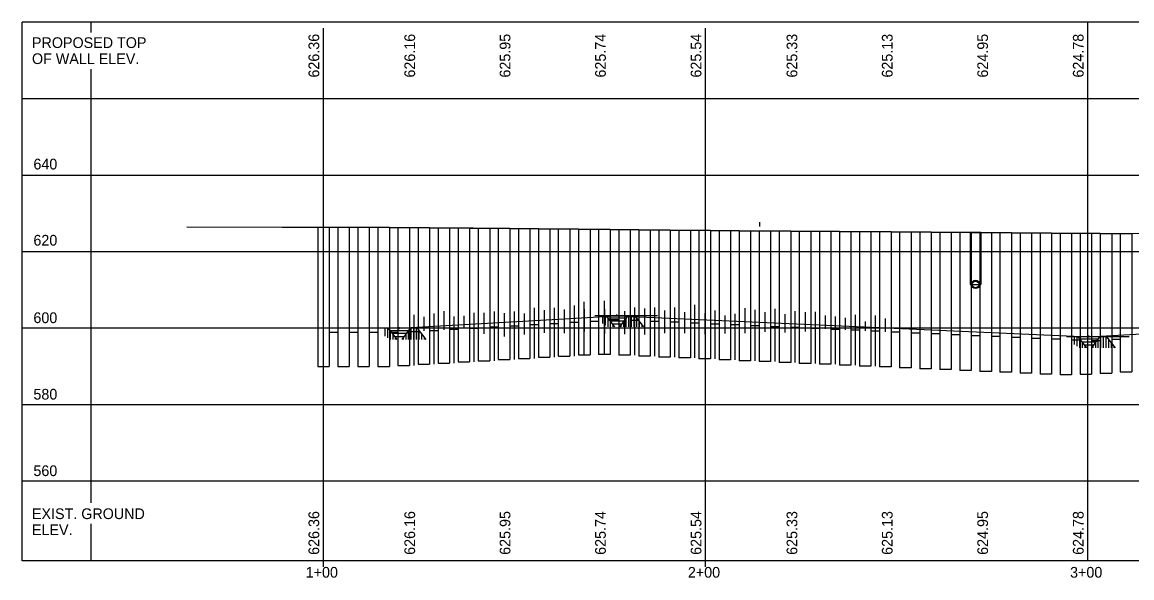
# Model space of a CAD drawing. Extents: x 2267596 to 2268160, y 712626 to 714793.
# Drawn here: x 2267595.7 to 2267886, y 713757.9 to 713903.3 of the extents above; entities that cross this region are included whole.
import ezdxf

# ---------------------------------------------------------------- set-up
doc = ezdxf.new("R2010")
doc.units = 0
for name, color, linetype in [('BR_P_Gen_Text', 7, 'Continuous'), ('BR_P_Sub_Deep_Hidden', 7, 'Continuous'), ('BR_P_Sub_Deep_Object', 7, 'Continuous'), ('Default', 7, 'Continuous'), ('DR_P_Storm_Sewer', 7, 'Continuous'), ('GE_X_Alignment', 7, 'Continuous'), ('SC_Scratch1', 7, 'Continuous'), ('SC_Scratch10', 7, 'Continuous'), ('SC_Scratch9', 7, 'Continuous'), ('SC_Shading3', 7, 'Continuous'), ('SH_Major_Grid_Line', 7, 'Continuous'), ('XS_X_Ground_Line', 7, 'Continuous')]:
    doc.layers.add(name, color=color, linetype=linetype)

msp = doc.modelspace()

# ---------------------------------------------------------------- linework, layer by layer
at = {"layer": 'BR_P_Sub_Deep_Hidden'}
for p, q in [((2267843.78, 713848.35), (2267843.78, 713834.69)), ((2267846.53, 713848.32), (2267846.53, 713834.69)), ((2267844.08, 713834.69), (2267843.78, 713834.69)), ((2267846.53, 713834.69), (2267846.25, 713834.69))]:
    msp.add_line(p, q, dxfattribs=at)
at = {"layer": 'BR_P_Sub_Deep_Object'}
for p, q in [((2267673.03, 713849.7), (2267676.03, 713849.69)), ((2267673.03, 713849.69), (2267673.03, 713813.21)), ((2267676.03, 713849.69), (2267676.03, 713813.21)), ((2267676.03, 713849.69), (2267678.28, 713849.69)), ((2267678.28, 713849.69), (2267678.28, 713813.21)), ((2267678.28, 713849.69), (2267681.28, 713849.69)), ((2267681.28, 713849.69), (2267681.28, 713813.21)), ((2267681.28, 713849.69), (2267683.53, 713849.69)), ((2267683.53, 713849.69), (2267686.53, 713849.69)), ((2267683.53, 713849.68), (2267683.53, 713813.21)), ((2267686.53, 713849.69), (2267688.78, 713849.69)), ((2267686.53, 713849.68), (2267686.53, 713813.21)), ((2267688.78, 713849.68), (2267688.78, 713813.22)), ((2267688.78, 713849.66), (2267691.78, 713849.66)), ((2267691.78, 713849.66), (2267691.78, 713813.22)), ((2267691.78, 713849.63), (2267694.03, 713849.63)), ((2267694.03, 713849.63), (2267694.03, 713813.52)), ((2267694.03, 713849.62), (2267697.03, 713849.62)), ((2267697.03, 713849.61), (2267697.03, 713813.52)), ((2267697.03, 713849.59), (2267699.28, 713849.59)), ((2267699.28, 713849.59), (2267699.28, 713813.83)), ((2267699.28, 713849.57), (2267702.28, 713849.57)), ((2267702.28, 713849.57), (2267702.28, 713813.83)), ((2267702.28, 713849.54), (2267704.53, 713849.54)), ((2267704.53, 713849.54), (2267704.53, 713814.13)), ((2267704.53, 713849.52), (2267707.53, 713849.52)), ((2267707.53, 713849.52), (2267707.53, 713814.13)), ((2267707.53, 713849.5), (2267709.78, 713849.5)), ((2267709.78, 713849.49), (2267709.78, 713814.44)), ((2267709.78, 713849.48), (2267712.78, 713849.48)), ((2267712.78, 713849.47), (2267712.78, 713814.44)), ((2267712.78, 713849.45), (2267715.03, 713849.45)), ((2267715.03, 713849.45), (2267715.03, 713814.74)), ((2267715.03, 713849.43), (2267718.03, 713849.43)), ((2267718.03, 713849.42), (2267718.03, 713814.74)), ((2267718.03, 713849.4), (2267720.28, 713849.4)), ((2267720.28, 713849.4), (2267720.28, 713815.04)), ((2267720.28, 713849.38), (2267723.28, 713849.38)), ((2267723.28, 713849.37), (2267723.28, 713815.04)), ((2267723.28, 713849.35), (2267725.53, 713849.35)), ((2267725.53, 713849.35), (2267725.53, 713815.35)), ((2267725.53, 713849.33), (2267728.53, 713849.33)), ((2267728.53, 713849.32), (2267728.53, 713815.35)), ((2267728.53, 713849.3), (2267730.78, 713849.3)), ((2267730.78, 713849.3), (2267730.78, 713815.65)), ((2267730.78, 713849.28), (2267733.78, 713849.28)), ((2267733.78, 713849.27), (2267733.78, 713815.65)), ((2267733.78, 713849.25), (2267736.03, 713849.25)), ((2267736.03, 713815.96), (2267736.03, 713849.24)), ((2267736.03, 713849.23), (2267739.03, 713849.23)), ((2267739.03, 713849.22), (2267739.03, 713815.96)), ((2267739.03, 713849.2), (2267741.28, 713849.2)), ((2267741.28, 713849.19), (2267741.28, 713816.26)), ((2267741.28, 713849.17), (2267744.28, 713849.17)), ((2267744.28, 713849.17), (2267744.28, 713816.26)), ((2267744.28, 713849.14), (2267746.53, 713849.14)), ((2267746.53, 713849.14), (2267746.53, 713816.37)), ((2267746.53, 713849.12), (2267749.53, 713849.12)), ((2267749.53, 713849.12), (2267749.53, 713816.37)), ((2267749.53, 713849.09), (2267751.78, 713849.09)), ((2267751.78, 713849.09), (2267751.78, 713816.14)), ((2267751.78, 713849.07), (2267754.78, 713849.07)), ((2267754.78, 713849.07), (2267754.78, 713816.14)), ((2267754.78, 713849.04), (2267757.03, 713849.04)), ((2267757.03, 713849.04), (2267757.03, 713815.9)), ((2267757.03, 713849.02), (2267760.03, 713849.02)), ((2267760.03, 713849.01), (2267760.03, 713815.9)), ((2267760.03, 713848.99), (2267762.28, 713848.99)), ((2267762.28, 713848.98), (2267762.28, 713815.67)), ((2267762.28, 713848.96), (2267765.28, 713848.96)), ((2267765.28, 713848.96), (2267765.28, 713815.67)), ((2267765.28, 713848.93), (2267767.53, 713848.93)), ((2267767.53, 713848.93), (2267767.53, 713815.44)), ((2267767.53, 713848.91), (2267770.53, 713848.91)), ((2267770.53, 713848.91), (2267770.53, 713815.44)), ((2267770.53, 713848.88), (2267772.78, 713848.88)), ((2267772.78, 713848.88), (2267772.78, 713815.2)), ((2267772.78, 713848.86), (2267775.78, 713848.86)), ((2267775.78, 713848.86), (2267775.78, 713815.2)), ((2267775.78, 713848.83), (2267778.03, 713848.83)), ((2267778.03, 713848.83), (2267778.03, 713814.97)), ((2267778.03, 713848.81), (2267781.03, 713848.81)), ((2267781.03, 713848.8), (2267781.03, 713814.97)), ((2267781.03, 713848.78), (2267783.28, 713848.78)), ((2267783.28, 713848.77), (2267783.28, 713814.73)), ((2267783.28, 713848.75), (2267786.28, 713848.75)), ((2267786.28, 713848.75), (2267786.28, 713814.73)), ((2267786.28, 713848.72), (2267788.53, 713848.72)), ((2267788.53, 713848.72), (2267788.53, 713814.5)), ((2267788.53, 713848.71), (2267791.53, 713848.71)), ((2267791.53, 713848.71), (2267791.53, 713814.5)), ((2267791.53, 713848.69), (2267793.78, 713848.69)), ((2267793.78, 713848.69), (2267793.78, 713814.27)), ((2267793.78, 713848.68), (2267796.78, 713848.68)), ((2267796.78, 713848.67), (2267796.78, 713814.27)), ((2267796.78, 713848.66), (2267799.03, 713848.66)), ((2267799.03, 713848.65), (2267799.03, 713814.03)), ((2267799.03, 713848.64), (2267802.03, 713848.64)), ((2267802.03, 713848.64), (2267802.03, 713814.03)), ((2267802.03, 713848.62), (2267804.28, 713848.62)), ((2267804.28, 713848.62), (2267804.28, 713813.8)), ((2267804.28, 713848.61), (2267807.28, 713848.61)), ((2267807.28, 713848.61), (2267807.28, 713813.8)), ((2267807.28, 713848.59), (2267809.53, 713848.59)), ((2267809.53, 713848.59), (2267809.53, 713813.56)), ((2267809.53, 713848.58), (2267812.53, 713848.58)), ((2267812.53, 713848.57), (2267812.53, 713813.56)), ((2267812.53, 713848.56), (2267814.78, 713848.56)), ((2267814.78, 713848.55), (2267814.78, 713813.33)), ((2267814.78, 713848.54), (2267817.78, 713848.54)), ((2267817.78, 713848.54), (2267817.78, 713813.33)), ((2267817.78, 713848.52), (2267820.03, 713848.52)), ((2267820.03, 713848.52), (2267820.03, 713813.1)), ((2267820.03, 713848.5), (2267823.03, 713848.5)), ((2267823.03, 713848.5), (2267823.03, 713813.1)), ((2267823.03, 713848.48), (2267825.28, 713848.48)), ((2267825.28, 713848.48), (2267825.28, 713812.86)), ((2267825.28, 713848.47), (2267828.28, 713848.47)), ((2267828.28, 713848.47), (2267828.28, 713812.86)), ((2267828.28, 713848.45), (2267830.53, 713848.45)), ((2267830.53, 713848.45), (2267830.53, 713812.63)), ((2267830.53, 713848.43), (2267833.53, 713848.43)), ((2267833.53, 713848.43), (2267833.53, 713812.63)), ((2267833.53, 713848.41), (2267835.78, 713848.41)), ((2267835.78, 713848.41), (2267835.78, 713812.4)), ((2267835.78, 713848.4), (2267838.78, 713848.4)), ((2267838.78, 713848.39), (2267838.78, 713812.4)), ((2267838.78, 713848.37), (2267841.03, 713848.37)), ((2267841.03, 713848.37), (2267841.03, 713812.16)), ((2267841.03, 713848.35), (2267844.03, 713848.35)), ((2267844.03, 713848.35), (2267844.03, 713812.16)), ((2267844.03, 713848.32), (2267846.28, 713848.32)), ((2267846.28, 713848.32), (2267846.28, 713811.93)), ((2267846.28, 713848.3), (2267849.28, 713848.3)), ((2267849.28, 713848.29), (2267849.28, 713811.93)), ((2267849.28, 713848.27), (2267851.53, 713848.27)), ((2267851.53, 713848.27), (2267851.53, 713811.69)), ((2267851.53, 713848.25), (2267854.53, 713848.25)), ((2267854.53, 713848.24), (2267854.53, 713811.69)), ((2267854.53, 713848.22), (2267856.78, 713848.22)), ((2267856.78, 713848.22), (2267856.78, 713811.46)), ((2267856.78, 713848.2), (2267859.78, 713848.2)), ((2267859.78, 713848.19), (2267859.78, 713811.46)), ((2267859.78, 713848.17), (2267862.03, 713848.17)), ((2267862.03, 713848.17), (2267862.03, 713811.23)), ((2267862.03, 713848.15), (2267865.03, 713848.15)), ((2267865.03, 713848.15), (2267865.03, 713811.23)), ((2267865.03, 713848.13), (2267867.28, 713848.13)), ((2267867.28, 713848.13), (2267867.28, 713811.04)), ((2267867.28, 713848.12), (2267870.28, 713848.12)), ((2267870.28, 713848.12), (2267870.28, 713811.04)), ((2267870.28, 713848.1), (2267872.53, 713848.1)), ((2267872.53, 713848.1), (2267872.53, 713811.21)), ((2267872.53, 713848.09), (2267875.53, 713848.09)), ((2267875.53, 713848.08), (2267875.53, 713811.21)), ((2267875.53, 713848.07), (2267877.78, 713848.07)), ((2267877.78, 713848.07), (2267877.78, 713811.5)), ((2267877.78, 713848.05), (2267880.78, 713848.05)), ((2267880.78, 713848.05), (2267880.78, 713811.5)), ((2267880.78, 713848.04), (2267883.03, 713848.04)), ((2267883.03, 713848.03), (2267883.03, 713811.8)), ((2267883.03, 713848.02), (2267886.03, 713848.02)), ((2267886.03, 713848.02), (2267886.03, 713811.8)), ((2267744.28, 713825.1), (2267746.53, 713825.1)), ((2267751.78, 713825.41), (2267749.53, 713825.41)), ((2267757.03, 713825.26), (2267754.78, 713825.26)), ((2267762.28, 713825.02), (2267760.03, 713825.02)), ((2267676.03, 713822.21), (2267678.28, 713822.21)), ((2267681.28, 713822.21), (2267683.53, 713822.21)), ((2267686.53, 713822.21), (2267688.78, 713822.21)), ((2267691.78, 713822.21), (2267694.03, 713822.21)), ((2267697.03, 713822.37), (2267699.28, 713822.37)), ((2267702.28, 713822.67), (2267704.53, 713822.67)), ((2267707.53, 713822.97), (2267709.78, 713822.97)), ((2267712.78, 713823.28), (2267715.03, 713823.28)), ((2267718.03, 713823.58), (2267720.28, 713823.58)), ((2267723.28, 713823.89), (2267725.53, 713823.89)), ((2267728.53, 713824.19), (2267730.78, 713824.19)), ((2267733.78, 713824.5), (2267736.03, 713824.5)), ((2267739.03, 713824.8), (2267741.28, 713824.8)), ((2267767.53, 713824.79), (2267765.28, 713824.79)), ((2267772.78, 713824.56), (2267770.53, 713824.56)), ((2267778.03, 713824.32), (2267775.78, 713824.32)), ((2267783.28, 713824.09), (2267781.03, 713824.09)), ((2267788.53, 713823.85), (2267786.28, 713823.85)), ((2267793.78, 713823.62), (2267791.53, 713823.62)), ((2267799.03, 713823.39), (2267796.78, 713823.39)), ((2267804.28, 713823.15), (2267802.03, 713823.15)), ((2267809.53, 713822.92), (2267807.28, 713822.92)), ((2267814.78, 713822.69), (2267812.53, 713822.69)), ((2267820.03, 713822.45), (2267817.78, 713822.45)), ((2267825.28, 713822.22), (2267823.03, 713822.22)), ((2267830.53, 713821.98), (2267828.28, 713821.98)), ((2267835.78, 713821.75), (2267833.53, 713821.75)), ((2267841.03, 713821.52), (2267838.78, 713821.52)), ((2267846.28, 713821.28), (2267844.03, 713821.28)), ((2267851.53, 713821.05), (2267849.28, 713821.05)), ((2267856.78, 713820.81), (2267854.53, 713820.81)), ((2267862.03, 713820.58), (2267859.78, 713820.58)), ((2267867.28, 713820.35), (2267865.03, 713820.35)), ((2267872.53, 713820.11), (2267870.28, 713820.11)), ((2267875.53, 713820.05), (2267877.78, 713820.05)), ((2267880.78, 713820.35), (2267883.03, 713820.35)), ((2267749.53, 713816.37), (2267746.53, 713816.37)), ((2267694.03, 713813.52), (2267697.03, 713813.52)), ((2267699.28, 713813.83), (2267702.28, 713813.83)), ((2267704.53, 713814.13), (2267707.53, 713814.13)), ((2267709.78, 713814.44), (2267712.78, 713814.44)), ((2267715.03, 713814.74), (2267718.03, 713814.74)), ((2267720.28, 713815.04), (2267723.28, 713815.04)), ((2267725.53, 713815.35), (2267728.53, 713815.35)), ((2267730.78, 713815.65), (2267733.78, 713815.65)), ((2267736.03, 713815.96), (2267739.03, 713815.96)), ((2267741.28, 713816.26), (2267744.28, 713816.26)), ((2267754.78, 713816.14), (2267751.78, 713816.14)), ((2267760.03, 713815.9), (2267757.03, 713815.9)), ((2267765.28, 713815.67), (2267762.28, 713815.67)), ((2267770.53, 713815.44), (2267767.53, 713815.44)), ((2267775.78, 713815.2), (2267772.78, 713815.2)), ((2267781.03, 713814.97), (2267778.03, 713814.97)), ((2267786.28, 713814.73), (2267783.28, 713814.73)), ((2267791.53, 713814.5), (2267788.53, 713814.5)), ((2267796.78, 713814.27), (2267793.78, 713814.27)), ((2267802.03, 713814.03), (2267799.03, 713814.03)), ((2267807.28, 713813.8), (2267804.28, 713813.8)), ((2267812.53, 713813.56), (2267809.53, 713813.56)), ((2267673.03, 713813.21), (2267676.03, 713813.21)), ((2267678.28, 713813.21), (2267681.28, 713813.21)), ((2267683.53, 713813.21), (2267686.53, 713813.21)), ((2267688.78, 713813.22), (2267691.78, 713813.22)), ((2267817.78, 713813.33), (2267814.78, 713813.33)), ((2267823.03, 713813.1), (2267820.03, 713813.1)), ((2267828.28, 713812.86), (2267825.28, 713812.86)), ((2267833.53, 713812.63), (2267830.53, 713812.63)), ((2267838.78, 713812.4), (2267835.78, 713812.4)), ((2267844.03, 713812.16), (2267841.03, 713812.16)), ((2267849.28, 713811.93), (2267846.28, 713811.93)), ((2267854.53, 713811.69), (2267851.53, 713811.69)), ((2267859.78, 713811.46), (2267856.78, 713811.46)), ((2267865.03, 713811.23), (2267862.03, 713811.23)), ((2267870.28, 713811.04), (2267867.28, 713811.04)), ((2267872.53, 713811.21), (2267875.53, 713811.21)), ((2267877.78, 713811.5), (2267880.78, 713811.5)), ((2267883.03, 713811.8), (2267886.03, 713811.8))]:
    msp.add_line(p, q, dxfattribs=at)
at = {"layer": 'Default'}
for p, q in [((2267761.9, 713826.51), (2267745.5, 713826.51)), ((2267747.52, 713826.51), (2267747.52, 713824.45)), ((2267748.21, 713826.51), (2267748.21, 713824.02)), ((2267748.43, 713826.51), (2267750.7, 713823.56)), ((2267748.9, 713825.9), (2267748.9, 713823.56)), ((2267753.67, 713825.87), (2267748.9, 713825.87)), ((2267753.12, 713825.11), (2267749.51, 713825.11)), ((2267754.14, 713826.51), (2267752, 713823.56)), ((2267753.67, 713825.87), (2267753.67, 713823.56)), ((2267754.36, 713826.51), (2267754.36, 713823.56)), ((2267755.05, 713826.51), (2267755.05, 713823.56)), ((2267755.75, 713826.51), (2267755.75, 713823.56)), ((2267755.96, 713826.51), (2267758.24, 713823.56)), ((2267756.44, 713825.9), (2267756.44, 713823.56)), ((2267704.94, 713823.21), (2267688.55, 713823.21)), ((2267690.56, 713823.21), (2267690.56, 713821.15)), ((2267691.26, 713823.21), (2267691.26, 713820.72)), ((2267691.47, 713823.21), (2267693.75, 713820.26)), ((2267691.95, 713822.6), (2267691.95, 713820.26)), ((2267696.72, 713822.57), (2267691.95, 713822.57)), ((2267697.18, 713823.21), (2267695.05, 713820.26)), ((2267696.72, 713822.57), (2267696.72, 713820.26)), ((2267697.41, 713823.21), (2267697.41, 713820.26)), ((2267698.1, 713823.21), (2267698.1, 713820.26)), ((2267698.79, 713823.21), (2267698.79, 713820.26)), ((2267699.01, 713823.21), (2267701.29, 713820.26)), ((2267699.48, 713822.6), (2267699.48, 713820.26)), ((2267749.59, 713825), (2267749.59, 713823.56)), ((2267752.55, 713824.32), (2267750.11, 713824.32)), ((2267750.27, 713824.12), (2267750.27, 713823.56)), ((2267752.37, 713824.07), (2267752.37, 713823.56)), ((2267753.02, 713824.97), (2267753.02, 713823.56)), ((2267757.13, 713825), (2267757.13, 713823.56)), ((2267757.81, 713824.12), (2267757.81, 713823.56)), ((2267696.17, 713821.81), (2267692.55, 713821.81)), ((2267692.64, 713821.7), (2267692.64, 713820.26)), ((2267695.6, 713821.02), (2267693.16, 713821.02)), ((2267693.32, 713820.82), (2267693.32, 713820.26)), ((2267695.41, 713820.77), (2267695.41, 713820.26)), ((2267696.07, 713821.67), (2267696.07, 713820.26)), ((2267700.17, 713821.7), (2267700.17, 713820.26)), ((2267700.86, 713820.82), (2267700.86, 713820.26)), ((2267885.37, 713821.01), (2267868.98, 713821.01)), ((2267870.99, 713821.01), (2267870.99, 713818.95)), ((2267871.68, 713821.01), (2267871.68, 713818.52)), ((2267871.9, 713821.01), (2267874.18, 713818.06)), ((2267872.38, 713820.4), (2267872.38, 713818.06)), ((2267877.15, 713820.37), (2267872.38, 713820.37)), ((2267876.6, 713819.61), (2267872.98, 713819.61)), ((2267873.07, 713819.5), (2267873.07, 713818.06)), ((2267877.61, 713821.01), (2267875.48, 713818.06)), ((2267876.5, 713819.47), (2267876.5, 713818.06)), ((2267877.15, 713820.37), (2267877.15, 713818.06)), ((2267877.84, 713821.01), (2267877.84, 713818.06)), ((2267878.53, 713821.01), (2267878.53, 713818.06)), ((2267879.22, 713821.01), (2267879.22, 713818.06)), ((2267879.44, 713821.01), (2267881.72, 713818.06)), ((2267879.91, 713820.4), (2267879.91, 713818.06)), ((2267880.6, 713819.5), (2267880.6, 713818.06)), ((2267876.03, 713818.82), (2267873.59, 713818.82)), ((2267873.75, 713818.62), (2267873.75, 713818.06)), ((2267875.84, 713818.57), (2267875.84, 713818.06)), ((2267881.29, 713818.62), (2267881.29, 713818.06))]:
    msp.add_line(p, q, dxfattribs=at)
at = {"layer": 'DR_P_Storm_Sewer'}
for radius in [1.08, 0.876]:
    msp.add_circle((2267845.16, 713834.69), radius, dxfattribs=at)
at = {"layer": 'GE_X_Alignment'}
for p, q in [((2267613.74, 713900.65), (2267613.74, 713903.31)), ((2267674.53, 713760.76), (2267674.53, 713901.75)), ((2267774.53, 713760.76), (2267774.53, 713901.75)), ((2267874.53, 713762.33), (2267874.53, 713903.31)), ((2267613.74, 713777.52), (2267613.74, 713891.01)), ((2267595.7, 713883.31), (2268156.77, 713883.31)), ((2267595.7, 713863.31), (2268156.77, 713863.31)), ((2267595.7, 713843.31), (2268156.77, 713843.31)), ((2267595.7, 713823.31), (2268156.77, 713823.31)), ((2267595.7, 713803.31), (2268156.77, 713803.31)), ((2267595.7, 713783.31), (2268156.77, 713783.31)), ((2267613.74, 713762.33), (2267613.74, 713772.01))]:
    msp.add_line(p, q, dxfattribs=at)
at = {"layer": 'SC_Scratch1'}
for p, q in [((2267729.74, 713815.35), (2267729.74, 713828.53)), ((2267732.37, 713822.05), (2267732.37, 713827.96)), ((2267734.99, 713815.65), (2267734.99, 713828.58)), ((2267737.62, 713821.96), (2267737.62, 713828.11)), ((2267740.24, 713815.96), (2267740.24, 713829.16)), ((2267742.78, 713816.26), (2267742.78, 713830.17)), ((2267742.87, 713822.38), (2267742.87, 713828.22)), ((2267748.03, 713816.37), (2267748.03, 713830.4)), ((2267748.12, 713821.83), (2267748.12, 713828.21)), ((2267755.99, 713816.14), (2267755.99, 713828.68)), ((2267758.62, 713821.59), (2267758.62, 713828.35)), ((2267761.24, 713815.9), (2267761.24, 713828.65)), ((2267766.49, 713815.67), (2267766.49, 713828.62)), ((2267771.74, 713815.44), (2267771.74, 713829.35)), ((2267784.87, 713821.95), (2267784.87, 713828.45)), ((2267787.49, 713814.73), (2267787.49, 713828.03)), ((2267792.74, 713814.5), (2267792.74, 713828.34)), ((2267698.24, 713813.52), (2267698.24, 713826.72)), ((2267700.87, 713822.52), (2267700.87, 713826.21)), ((2267703.49, 713813.83), (2267703.49, 713827.05)), ((2267706.12, 713822.83), (2267706.12, 713827.71)), ((2267708.74, 713814.13), (2267708.74, 713826.33)), ((2267711.37, 713823.13), (2267711.37, 713826.44)), ((2267713.99, 713814.44), (2267713.99, 713827.22)), ((2267716.62, 713821.77), (2267716.62, 713827.22)), ((2267719.24, 713814.74), (2267719.24, 713827.59)), ((2267721.87, 713821.07), (2267721.87, 713827.17)), ((2267724.49, 713815.04), (2267724.49, 713827.64)), ((2267727.12, 713821.63), (2267727.12, 713827.07)), ((2267753.37, 713821.65), (2267753.37, 713827.72)), ((2267763.87, 713821.92), (2267763.87, 713827.89)), ((2267769.12, 713821.92), (2267769.12, 713827.41)), ((2267774.37, 713821.72), (2267774.37, 713827.15)), ((2267776.99, 713815.2), (2267776.99, 713827.89)), ((2267779.62, 713821.83), (2267779.62, 713826.58)), ((2267782.24, 713814.97), (2267782.24, 713827.03)), ((2267790.12, 713822.31), (2267790.12, 713827.4)), ((2267795.37, 713822.15), (2267795.37, 713826.88)), ((2267797.99, 713814.27), (2267797.99, 713827.72)), ((2267800.62, 713822.41), (2267800.62, 713827.47)), ((2267803.24, 713814.03), (2267803.24, 713827.56)), ((2267805.87, 713823.03), (2267805.87, 713826.6)), ((2267808.49, 713813.8), (2267808.49, 713826.28)), ((2267811.12, 713822.8), (2267811.12, 713825.95)), ((2267813.74, 713813.56), (2267813.74, 713826.72)), ((2267816.37, 713822.56), (2267816.37, 713825.02)), ((2267818.99, 713813.33), (2267818.99, 713826.52)), ((2267821.62, 713822.33), (2267821.62, 713825.74))]:
    msp.add_line(p, q, dxfattribs=at)
at = {"layer": 'SC_Scratch10'}
msp.add_line((2267788.74, 713849.82), (2267788.74, 713850.99), dxfattribs=at)
at = {"layer": 'SC_Scratch9'}
for p, q in [((2267751.31, 713826.29), (2267751.31, 713826.82)), ((2267694.36, 713822.99), (2267694.36, 713823.52)), ((2267874.79, 713820.79), (2267874.79, 713821.32))]:
    msp.add_line(p, q, dxfattribs=at)
at = {"layer": 'SC_Shading3'}
msp.add_lwpolyline([(2267843.78, 713834.69), (2267846.53, 713834.69), (2267846.53, 713848.3), (2267843.78, 713848.3)], close=True, dxfattribs=at)
at = {"layer": 'SH_Major_Grid_Line'}
for p, q in [((2267595.7, 713762.33), (2267595.7, 713903.31)), ((2268156.77, 713903.31), (2267595.7, 713903.31)), ((2268156.77, 713762.33), (2267595.7, 713762.33))]:
    msp.add_line(p, q, dxfattribs=at)
at = {"layer": 'XS_X_Ground_Line'}
msp.add_line((2267694.36, 713823.21), (2267671.93, 713823.21), dxfattribs=at)
for points in [[(2267638.74, 713849.74), (2267663.74, 713849.7), (2267688.74, 713849.68), (2267713.74, 713849.46), (2267738.74, 713849.22), (2267788.74, 713848.72), (2267813.74, 713848.56), (2267838.74, 713848.39), (2267863.74, 713848.15), (2267888.74, 713848), (2267913.74, 713847.83), (2267938.74, 713847.63), (2267963.74, 713847.69), (2267988.74, 713847.62), (2268013.74, 713847.41), (2268049.99, 713847.18)], [(2267694.36, 713823.21), (2267751.31, 713826.51), (2267874.79, 713821.01), (2267952.95, 713825.41), (2268025.6, 713821.91)]]:
    msp.add_lwpolyline(points, dxfattribs=at)

# ---------------------------------------------------------------- texts
at = {"layer": 'BR_P_Gen_Text'}
for s, p in [('PROPOSED TOP ', (2267598.26, 713896.56)), ('OF WALL ELEV.', (2267598.26, 713892.36)), ('640', (2267598.64, 713864.78)), ('620', (2267598.64, 713844.85)), ('600', (2267598.64, 713824.58)), ('580', (2267598.64, 713804.56)), ('560', (2267598.64, 713784.54)), ('EXIST. GROUND', (2267598.26, 713773.29)), ('ELEV.', (2267598.26, 713769.09)), ('1+00', (2267669.88, 713757.96)), ('2+00', (2267769.88, 713757.96)), ('3+00', (2267869.88, 713757.96))]:
    msp.add_text(s, height=2.8, dxfattribs=at).set_placement(p)
for s, p in [('626.36', (2267673.42, 713888.82)), ('626.16', (2267698.51, 713888.82)), ('625.95', (2267723.44, 713888.82)), ('625.74', (2267748.41, 713888.82)), ('625.54', (2267773.42, 713888.82)), ('625.33', (2267798.51, 713888.82)), ('625.13', (2267823.44, 713888.82)), ('624.95', (2267848.41, 713888.82)), ('624.78', (2267873.42, 713888.82)), ('626.36', (2267673.42, 713763.93)), ('626.16', (2267698.51, 713763.93)), ('625.95', (2267723.44, 713763.93)), ('625.74', (2267748.41, 713763.93)), ('625.54', (2267773.42, 713763.93)), ('625.33', (2267798.51, 713763.93)), ('625.13', (2267823.44, 713763.93)), ('624.95', (2267848.41, 713763.93)), ('624.78', (2267873.42, 713763.93))]:
    msp.add_text(s, height=2.8, rotation=90, dxfattribs=at).set_placement(p)

doc.saveas('drawing.dxf')
